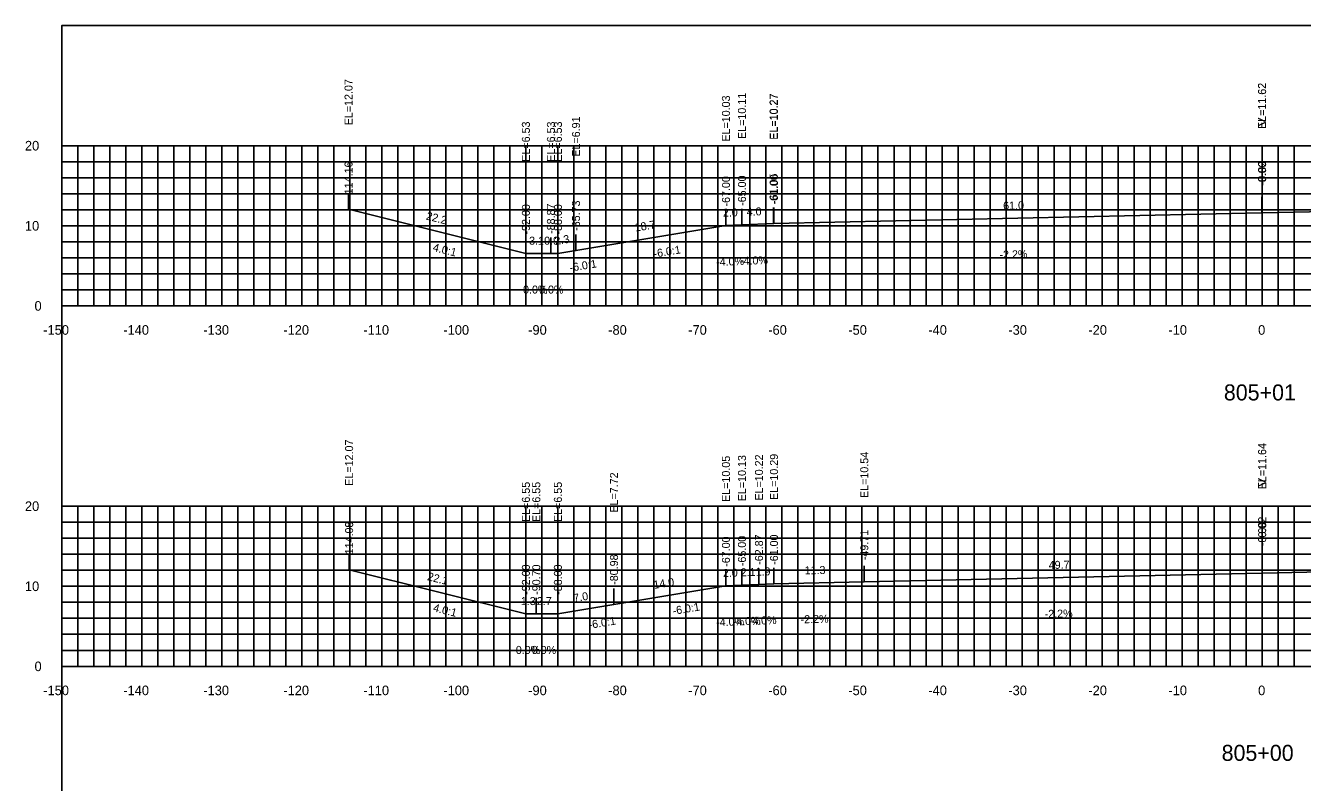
# Model space of a CAD drawing. Extents: x 1797419 to 1809236, y 248759 to 251512.
# Drawn here: x 1802824.4 to 1802984, y 249853.2 to 249947.7 of the extents above; entities that cross this region are included whole.
import ezdxf

# ---------------------------------------------------------------- set-up
doc = ezdxf.new("R2010")
doc.units = 0
for name, color, linetype in [('1', 7, 'Continuous'), ('10', 7, 'Continuous'), ('3', 7, 'Continuous'), ('31', 7, 'Continuous'), ('4', 7, 'Continuous'), ('60', 7, 'Continuous'), ('CL-CNST', 7, 'Continuous'), ('Level 62', 7, 'Continuous')]:
    doc.layers.add(name, color=color, linetype=linetype)

msp = doc.modelspace()

# ---------------------------------------------------------------- linework, layer by layer
for p, q in [((1802864.77, 249924.8), (1802864.77, 249926.8)), ((1802978.91, 249924.34), (1802978.91, 249926.34)), ((1802978.93, 249924.34), (1802978.93, 249926.34)), ((1802911.93, 249922.76), (1802911.93, 249924.76)), ((1802913.93, 249922.84), (1802913.93, 249924.84)), ((1802917.88, 249922.99), (1802917.88, 249924.99)), ((1802917.93, 249923), (1802917.93, 249925)), ((1802886.93, 249919.26), (1802886.93, 249921.26)), ((1802890.06, 249919.26), (1802890.06, 249921.26)), ((1802890.93, 249919.26), (1802890.93, 249921.26)), ((1802893.19, 249919.63), (1802893.19, 249921.63)), ((1802864.84, 249879.8), (1802864.84, 249881.8)), ((1802864.84, 249879.79), (1802864.84, 249881.79)), ((1802978.93, 249879.36), (1802978.93, 249881.36)), ((1802978.94, 249879.36), (1802978.94, 249881.36)), ((1802911.93, 249877.77), (1802911.93, 249879.77)), ((1802913.93, 249877.85), (1802913.93, 249879.85)), ((1802916.06, 249877.94), (1802916.06, 249879.94)), ((1802917.93, 249878.01), (1802917.93, 249880.01)), ((1802929.22, 249878.26), (1802929.22, 249880.26)), ((1802897.94, 249875.44), (1802897.94, 249877.44)), ((1802886.93, 249874.27), (1802886.93, 249876.27)), ((1802888.23, 249874.27), (1802888.23, 249876.27)), ((1802890.93, 249874.27), (1802890.93, 249876.27))]:
    msp.add_line(p, q)
msp.add_lwpolyline([(1802828.93, 249757.72), (1803128.93, 249757.72), (1803128.93, 249947.72), (1802828.93, 249947.72)], close=True)
at = {"layer": '60'}
for p, q in [((1802828.87, 249932.72), (1802828.93, 249932.72)), ((1802828.93, 249912.72), (1802828.93, 249932.72)), ((1802828.87, 249922.72), (1802828.93, 249922.72)), ((1802828.87, 249912.72), (1802828.93, 249912.72)), ((1802828.93, 249912.72), (1803128.93, 249912.72)), ((1802828.93, 249912.66), (1802828.93, 249912.72)), ((1802838.93, 249912.66), (1802838.93, 249912.72)), ((1802848.93, 249912.66), (1802848.93, 249912.72)), ((1802858.93, 249912.66), (1802858.93, 249912.72)), ((1802868.93, 249912.66), (1802868.93, 249912.72)), ((1802878.93, 249912.66), (1802878.93, 249912.72)), ((1802888.93, 249912.66), (1802888.93, 249912.72)), ((1802898.93, 249912.66), (1802898.93, 249912.72)), ((1802908.93, 249912.66), (1802908.93, 249912.72)), ((1802918.93, 249912.66), (1802918.93, 249912.72)), ((1802928.93, 249912.66), (1802928.93, 249912.72)), ((1802938.93, 249912.66), (1802938.93, 249912.72)), ((1802948.93, 249912.66), (1802948.93, 249912.72)), ((1802958.93, 249912.66), (1802958.93, 249912.72)), ((1802968.93, 249912.66), (1802968.93, 249912.72)), ((1802978.93, 249912.66), (1802978.93, 249912.72)), ((1802828.87, 249887.72), (1802828.93, 249887.72)), ((1802828.93, 249867.72), (1802828.93, 249887.72)), ((1802828.87, 249877.72), (1802828.93, 249877.72)), ((1802828.87, 249867.72), (1802828.93, 249867.72)), ((1802828.93, 249867.72), (1803128.93, 249867.72)), ((1802828.93, 249867.66), (1802828.93, 249867.72)), ((1802838.93, 249867.66), (1802838.93, 249867.72)), ((1802848.93, 249867.66), (1802848.93, 249867.72)), ((1802858.93, 249867.66), (1802858.93, 249867.72)), ((1802868.93, 249867.66), (1802868.93, 249867.72)), ((1802878.93, 249867.66), (1802878.93, 249867.72)), ((1802888.93, 249867.66), (1802888.93, 249867.72)), ((1802898.93, 249867.66), (1802898.93, 249867.72)), ((1802908.93, 249867.66), (1802908.93, 249867.72)), ((1802918.93, 249867.66), (1802918.93, 249867.72)), ((1802928.93, 249867.66), (1802928.93, 249867.72)), ((1802938.93, 249867.66), (1802938.93, 249867.72)), ((1802948.93, 249867.66), (1802948.93, 249867.72)), ((1802958.93, 249867.66), (1802958.93, 249867.72)), ((1802968.93, 249867.66), (1802968.93, 249867.72)), ((1802978.93, 249867.66), (1802978.93, 249867.72))]:
    msp.add_line(p, q, dxfattribs=at)
at = {"layer": 'CL-CNST'}
for points in [[(1802864.77, 249924.8), (1802886.93, 249919.26), (1802890.06, 249919.26), (1802890.93, 249919.26), (1802893.19, 249919.63), (1802911.93, 249922.76), (1802913.93, 249922.84), (1802917.88, 249922.99), (1802917.93, 249923), (1802978.91, 249924.34), (1802978.93, 249924.34), (1803004.61, 249924.9), (1803029.47, 249925.45), (1803033.47, 249925.29), (1803035.33, 249925.22), (1803035.47, 249925.21), (1803036.02, 249925.12), (1803056.47, 249921.71), (1803060.46, 249921.71), (1803093.13, 249923.34), (1803128.93, 249925.13)], [(1802864.84, 249879.8), (1802864.84, 249879.79), (1802886.93, 249874.27), (1802888.23, 249874.27), (1802890.93, 249874.27), (1802897.94, 249875.44), (1802911.93, 249877.77), (1802913.93, 249877.85), (1802916.06, 249877.94), (1802917.93, 249878.01), (1802929.22, 249878.26), (1802978.93, 249879.36), (1802978.94, 249879.36), (1803025.35, 249880.38), (1803029.55, 249880.47), (1803033.55, 249880.31), (1803035.55, 249880.23), (1803056.35, 249876.76), (1803056.55, 249876.73), (1803056.6, 249876.73), (1803060.55, 249876.73), (1803121.79, 249879.79), (1803128.93, 249880.15)]]:
    msp.add_lwpolyline(points, dxfattribs=at)
at = {"layer": 'Level 62'}
for p, q in [((1802828.93, 249932.72), (1803128.93, 249932.72)), ((1802828.93, 249912.72), (1802828.93, 249932.72)), ((1802830.93, 249912.72), (1802830.93, 249932.72)), ((1802832.93, 249912.72), (1802832.93, 249932.72)), ((1802834.93, 249912.72), (1802834.93, 249932.72)), ((1802836.93, 249912.72), (1802836.93, 249932.72)), ((1802838.93, 249912.72), (1802838.93, 249932.72)), ((1802840.93, 249912.72), (1802840.93, 249932.72)), ((1802842.93, 249912.72), (1802842.93, 249932.72)), ((1802844.93, 249912.72), (1802844.93, 249932.72)), ((1802846.93, 249912.72), (1802846.93, 249932.72)), ((1802848.93, 249912.72), (1802848.93, 249932.72)), ((1802850.93, 249912.72), (1802850.93, 249932.72)), ((1802852.93, 249912.72), (1802852.93, 249932.72)), ((1802854.93, 249912.72), (1802854.93, 249932.72)), ((1802856.93, 249912.72), (1802856.93, 249932.72)), ((1802858.93, 249912.72), (1802858.93, 249932.72)), ((1802860.93, 249912.72), (1802860.93, 249932.72)), ((1802862.93, 249912.72), (1802862.93, 249932.72)), ((1802864.93, 249912.72), (1802864.93, 249932.72)), ((1802866.93, 249912.72), (1802866.93, 249932.72)), ((1802868.93, 249912.72), (1802868.93, 249932.72)), ((1802870.93, 249912.72), (1802870.93, 249932.72)), ((1802872.93, 249912.72), (1802872.93, 249932.72)), ((1802874.93, 249912.72), (1802874.93, 249932.72)), ((1802876.93, 249912.72), (1802876.93, 249932.72)), ((1802878.93, 249912.72), (1802878.93, 249932.72)), ((1802880.93, 249912.72), (1802880.93, 249932.72)), ((1802882.93, 249912.72), (1802882.93, 249932.72)), ((1802884.93, 249912.72), (1802884.93, 249932.72)), ((1802886.93, 249912.72), (1802886.93, 249932.72)), ((1802888.93, 249912.72), (1802888.93, 249932.72)), ((1802890.93, 249912.72), (1802890.93, 249932.72)), ((1802892.93, 249912.72), (1802892.93, 249932.72)), ((1802894.93, 249912.72), (1802894.93, 249932.72)), ((1802896.93, 249912.72), (1802896.93, 249932.72)), ((1802898.93, 249912.72), (1802898.93, 249932.72)), ((1802900.93, 249912.72), (1802900.93, 249932.72)), ((1802902.93, 249912.72), (1802902.93, 249932.72)), ((1802904.93, 249912.72), (1802904.93, 249932.72)), ((1802906.93, 249912.72), (1802906.93, 249932.72)), ((1802908.93, 249912.72), (1802908.93, 249932.72)), ((1802910.93, 249912.72), (1802910.93, 249932.72)), ((1802912.93, 249912.72), (1802912.93, 249932.72)), ((1802914.93, 249912.72), (1802914.93, 249932.72)), ((1802916.93, 249912.72), (1802916.93, 249932.72)), ((1802918.93, 249912.72), (1802918.93, 249932.72)), ((1802920.93, 249912.72), (1802920.93, 249932.72)), ((1802922.93, 249912.72), (1802922.93, 249932.72)), ((1802924.93, 249912.72), (1802924.93, 249932.72)), ((1802926.93, 249912.72), (1802926.93, 249932.72)), ((1802928.93, 249912.72), (1802928.93, 249932.72)), ((1802930.93, 249912.72), (1802930.93, 249932.72)), ((1802932.93, 249912.72), (1802932.93, 249932.72)), ((1802934.93, 249912.72), (1802934.93, 249932.72)), ((1802936.93, 249912.72), (1802936.93, 249932.72)), ((1802938.93, 249912.72), (1802938.93, 249932.72)), ((1802940.93, 249912.72), (1802940.93, 249932.72)), ((1802942.93, 249912.72), (1802942.93, 249932.72)), ((1802944.93, 249912.72), (1802944.93, 249932.72)), ((1802946.93, 249912.72), (1802946.93, 249932.72)), ((1802948.93, 249912.72), (1802948.93, 249932.72)), ((1802950.93, 249912.72), (1802950.93, 249932.72)), ((1802952.93, 249912.72), (1802952.93, 249932.72)), ((1802954.93, 249912.72), (1802954.93, 249932.72)), ((1802956.93, 249912.72), (1802956.93, 249932.72)), ((1802958.93, 249912.72), (1802958.93, 249932.72)), ((1802960.93, 249912.72), (1802960.93, 249932.72)), ((1802962.93, 249912.72), (1802962.93, 249932.72)), ((1802964.93, 249912.72), (1802964.93, 249932.72)), ((1802966.93, 249912.72), (1802966.93, 249932.72)), ((1802968.93, 249912.72), (1802968.93, 249932.72)), ((1802970.93, 249912.72), (1802970.93, 249932.72)), ((1802972.93, 249912.72), (1802972.93, 249932.72)), ((1802974.93, 249912.72), (1802974.93, 249932.72)), ((1802976.93, 249912.72), (1802976.93, 249932.72)), ((1802978.93, 249912.72), (1802978.93, 249932.72)), ((1802980.93, 249912.72), (1802980.93, 249932.72)), ((1802982.93, 249912.72), (1802982.93, 249932.72)), ((1802828.93, 249930.72), (1803128.93, 249930.72)), ((1802828.93, 249928.72), (1803128.93, 249928.72)), ((1802828.93, 249926.72), (1803128.93, 249926.72)), ((1802828.93, 249924.72), (1803128.93, 249924.72)), ((1802828.93, 249922.72), (1803128.93, 249922.72)), ((1802828.93, 249920.72), (1803128.93, 249920.72)), ((1802828.93, 249918.72), (1803128.93, 249918.72)), ((1802828.93, 249916.72), (1803128.93, 249916.72)), ((1802828.93, 249914.72), (1803128.93, 249914.72)), ((1802828.93, 249912.72), (1803128.93, 249912.72)), ((1802828.93, 249887.72), (1803128.93, 249887.72)), ((1802828.93, 249867.72), (1802828.93, 249887.72)), ((1802830.93, 249867.72), (1802830.93, 249887.72)), ((1802832.93, 249867.72), (1802832.93, 249887.72)), ((1802834.93, 249867.72), (1802834.93, 249887.72)), ((1802836.93, 249867.72), (1802836.93, 249887.72)), ((1802838.93, 249867.72), (1802838.93, 249887.72)), ((1802840.93, 249867.72), (1802840.93, 249887.72)), ((1802842.93, 249867.72), (1802842.93, 249887.72)), ((1802844.93, 249867.72), (1802844.93, 249887.72)), ((1802846.93, 249867.72), (1802846.93, 249887.72)), ((1802848.93, 249867.72), (1802848.93, 249887.72)), ((1802850.93, 249867.72), (1802850.93, 249887.72)), ((1802852.93, 249867.72), (1802852.93, 249887.72)), ((1802854.93, 249867.72), (1802854.93, 249887.72)), ((1802856.93, 249867.72), (1802856.93, 249887.72)), ((1802858.93, 249867.72), (1802858.93, 249887.72)), ((1802860.93, 249867.72), (1802860.93, 249887.72)), ((1802862.93, 249867.72), (1802862.93, 249887.72)), ((1802864.93, 249867.72), (1802864.93, 249887.72)), ((1802866.93, 249867.72), (1802866.93, 249887.72)), ((1802868.93, 249867.72), (1802868.93, 249887.72)), ((1802870.93, 249867.72), (1802870.93, 249887.72)), ((1802872.93, 249867.72), (1802872.93, 249887.72)), ((1802874.93, 249867.72), (1802874.93, 249887.72)), ((1802876.93, 249867.72), (1802876.93, 249887.72)), ((1802878.93, 249867.72), (1802878.93, 249887.72)), ((1802880.93, 249867.72), (1802880.93, 249887.72)), ((1802882.93, 249867.72), (1802882.93, 249887.72)), ((1802884.93, 249867.72), (1802884.93, 249887.72)), ((1802886.93, 249867.72), (1802886.93, 249887.72)), ((1802888.93, 249867.72), (1802888.93, 249887.72)), ((1802890.93, 249867.72), (1802890.93, 249887.72)), ((1802892.93, 249867.72), (1802892.93, 249887.72)), ((1802894.93, 249867.72), (1802894.93, 249887.72)), ((1802896.93, 249867.72), (1802896.93, 249887.72)), ((1802898.93, 249867.72), (1802898.93, 249887.72)), ((1802900.93, 249867.72), (1802900.93, 249887.72)), ((1802902.93, 249867.72), (1802902.93, 249887.72)), ((1802904.93, 249867.72), (1802904.93, 249887.72)), ((1802906.93, 249867.72), (1802906.93, 249887.72)), ((1802908.93, 249867.72), (1802908.93, 249887.72)), ((1802910.93, 249867.72), (1802910.93, 249887.72)), ((1802912.93, 249867.72), (1802912.93, 249887.72)), ((1802914.93, 249867.72), (1802914.93, 249887.72)), ((1802916.93, 249867.72), (1802916.93, 249887.72)), ((1802918.93, 249867.72), (1802918.93, 249887.72)), ((1802920.93, 249867.72), (1802920.93, 249887.72)), ((1802922.93, 249867.72), (1802922.93, 249887.72)), ((1802924.93, 249867.72), (1802924.93, 249887.72)), ((1802926.93, 249867.72), (1802926.93, 249887.72)), ((1802928.93, 249867.72), (1802928.93, 249887.72)), ((1802930.93, 249867.72), (1802930.93, 249887.72)), ((1802932.93, 249867.72), (1802932.93, 249887.72)), ((1802934.93, 249867.72), (1802934.93, 249887.72)), ((1802936.93, 249867.72), (1802936.93, 249887.72)), ((1802938.93, 249867.72), (1802938.93, 249887.72)), ((1802940.93, 249867.72), (1802940.93, 249887.72)), ((1802942.93, 249867.72), (1802942.93, 249887.72)), ((1802944.93, 249867.72), (1802944.93, 249887.72)), ((1802946.93, 249867.72), (1802946.93, 249887.72)), ((1802948.93, 249867.72), (1802948.93, 249887.72)), ((1802950.93, 249867.72), (1802950.93, 249887.72)), ((1802952.93, 249867.72), (1802952.93, 249887.72)), ((1802954.93, 249867.72), (1802954.93, 249887.72)), ((1802956.93, 249867.72), (1802956.93, 249887.72)), ((1802958.93, 249867.72), (1802958.93, 249887.72)), ((1802960.93, 249867.72), (1802960.93, 249887.72)), ((1802962.93, 249867.72), (1802962.93, 249887.72)), ((1802964.93, 249867.72), (1802964.93, 249887.72)), ((1802966.93, 249867.72), (1802966.93, 249887.72)), ((1802968.93, 249867.72), (1802968.93, 249887.72)), ((1802970.93, 249867.72), (1802970.93, 249887.72)), ((1802972.93, 249867.72), (1802972.93, 249887.72)), ((1802974.93, 249867.72), (1802974.93, 249887.72)), ((1802976.93, 249867.72), (1802976.93, 249887.72)), ((1802978.93, 249867.72), (1802978.93, 249887.72)), ((1802980.93, 249867.72), (1802980.93, 249887.72)), ((1802982.93, 249867.72), (1802982.93, 249887.72)), ((1802828.93, 249885.72), (1803128.93, 249885.72)), ((1802828.93, 249883.72), (1803128.93, 249883.72)), ((1802828.93, 249881.72), (1803128.93, 249881.72)), ((1802828.93, 249879.72), (1803128.93, 249879.72)), ((1802828.93, 249877.72), (1803128.93, 249877.72)), ((1802828.93, 249875.72), (1803128.93, 249875.72)), ((1802828.93, 249873.72), (1803128.93, 249873.72)), ((1802828.93, 249871.72), (1803128.93, 249871.72)), ((1802828.93, 249869.72), (1803128.93, 249869.72)), ((1802828.93, 249867.72), (1803128.93, 249867.72))]:
    msp.add_line(p, q, dxfattribs=at)

# ---------------------------------------------------------------- texts
for s, rotation, p in [('4.0:1', 345.9642, (1802875.24, 249919.6)), ('-6.0:1', 9.4623, (1802902.97, 249918.73)), ('-6.0:1', 9.4623, (1802892.47, 249916.98)), ('-6.0:1', 9.4623, (1802905.35, 249874.14)), ('4.0:1', 345.9644, (1802875.28, 249874.61)), ('-6.0:1', 9.4623, (1802894.85, 249872.39))]:
    msp.add_text(s, height=1, rotation=rotation).set_placement(p)
at = {"layer": '1'}
for s, p in [('805+01', (1802974.15, 249900.92)), ('805+00', (1802973.87, 249855.92))]:
    msp.add_text(s, height=2, dxfattribs=at).set_placement(p)
at = {"layer": '10'}
for s, p in [('-150', (1802826.62, 249909.12)), ('-140', (1802836.62, 249909.12)), ('-130', (1802846.62, 249909.12)), ('-120', (1802856.62, 249909.12)), ('-110', (1802866.62, 249909.12)), ('-100', (1802876.62, 249909.12)), ('-90', (1802887.22, 249909.12)), ('-80', (1802897.22, 249909.12)), ('-70', (1802907.22, 249909.12)), ('-60', (1802917.22, 249909.12)), ('-50', (1802927.22, 249909.12)), ('-40', (1802937.22, 249909.12)), ('-30', (1802947.22, 249909.12)), ('-20', (1802957.22, 249909.12)), ('-10', (1802967.22, 249909.12)), ('0', (1802978.43, 249909.12)), ('-150', (1802826.62, 249864.12)), ('-140', (1802836.62, 249864.12)), ('-130', (1802846.62, 249864.12)), ('-120', (1802856.62, 249864.12)), ('-110', (1802866.62, 249864.12)), ('-100', (1802876.62, 249864.12)), ('-90', (1802887.22, 249864.12)), ('-80', (1802897.22, 249864.12)), ('-70', (1802907.22, 249864.12)), ('-60', (1802917.22, 249864.12)), ('-50', (1802927.22, 249864.12)), ('-40', (1802937.22, 249864.12)), ('-30', (1802947.22, 249864.12)), ('-20', (1802957.22, 249864.12)), ('-10', (1802967.22, 249864.12)), ('0', (1802978.43, 249864.12))]:
    msp.add_text(s, height=1.2, dxfattribs=at).set_placement(p)
at = {"layer": '3'}
for s, p in [('EL=12.07', (1802865.27, 249935.27)), ('EL=11.62', (1802979.41, 249934.81)), ('EL=11.62', (1802979.43, 249934.81)), ('EL=10.03', (1802912.43, 249933.23)), ('EL=10.11', (1802914.43, 249933.56)), ('EL=10.27', (1802918.38, 249933.47)), ('EL=10.27', (1802918.43, 249933.47)), ('EL=6.91', (1802893.69, 249931.35)), ('EL=6.53', (1802887.43, 249930.72)), ('EL=6.53', (1802890.56, 249930.72)), ('EL=6.53', (1802891.43, 249930.72)), ('-114.16', (1802865.27, 249926.21)), ('-0.02', (1802979.41, 249927.79)), ('-0.00', (1802979.43, 249927.71)), ('-67.00', (1802912.43, 249925.13)), ('-65.00', (1802914.43, 249925.21)), ('-61.05', (1802918.38, 249925.45)), ('-61.00', (1802918.43, 249925.37)), ('-92.00', (1802887.43, 249921.63)), ('-88.87', (1802890.56, 249921.71)), ('-88.00', (1802891.43, 249921.63)), ('-85.73', (1802893.69, 249922.09)), ('EL=12.07', (1802865.34, 249890.27)), ('EL=12.07', (1802865.34, 249890.27)), ('EL=11.64', (1802979.43, 249889.83)), ('EL=11.64', (1802979.44, 249889.83)), ('EL=10.05', (1802912.43, 249888.25)), ('EL=10.13', (1802914.43, 249888.33)), ('EL=10.22', (1802916.56, 249888.41)), ('EL=10.29', (1802918.43, 249888.49)), ('EL=10.54', (1802929.72, 249888.74)), ('EL=7.72', (1802898.44, 249886.91)), ('EL=6.55', (1802887.43, 249885.74)), ('EL=6.55', (1802888.73, 249885.74)), ('EL=6.55', (1802891.43, 249885.74)), ('-114.09', (1802865.34, 249881.26)), ('-114.08', (1802865.34, 249881.26)), ('-0.00', (1802979.43, 249882.73)), ('0.02', (1802979.44, 249883.8)), ('-67.00', (1802912.43, 249880.15)), ('-65.00', (1802914.43, 249880.23)), ('-62.87', (1802916.56, 249880.4)), ('-61.00', (1802918.43, 249880.39)), ('-49.71', (1802929.72, 249880.97)), ('-80.98', (1802898.44, 249877.9)), ('-92.00', (1802887.43, 249876.65)), ('-90.70', (1802888.73, 249876.65)), ('-88.00', (1802891.43, 249876.65))]:
    msp.add_text(s, height=1, rotation=90, dxfattribs=at).set_placement(p)
at = {"layer": '31'}
for s, p in [('20', (1802824.33, 249932.12)), ('10', (1802824.33, 249922.12)), ('0', (1802825.53, 249912.12)), ('20', (1802824.33, 249887.12)), ('10', (1802824.33, 249877.12)), ('0', (1802825.53, 249867.12))]:
    msp.add_text(s, height=1.2, dxfattribs=at).set_placement(p)
at = {"layer": '4'}
for s, rotation, p in [('61.0', 1.2603, (1802946.58, 249924.73)), ('22.2', 345.9642, (1802874.39, 249923.52)), ('2.0', 2.2903, (1802911.56, 249923.84)), ('4.0', 2.2909, (1802914.54, 249923.96)), ('18.7', 9.4623, (1802900.62, 249921.99)), ('2.3', 9.4623, (1802890.61, 249920.32)), ('-4.0%', 2.2903, (1802910.72, 249917.7)), ('-4.0%', 2.2909, (1802913.7, 249917.82)), ('-2.2%', 1.2603, (1802946.12, 249918.62)), ('49.7', 1.2603, (1802952.27, 249879.87)), ('22.1', 345.9644, (1802874.55, 249878.5)), ('2.0', 2.2903, (1802911.56, 249878.86)), ('2.1', 2.2909, (1802913.79, 249878.95)), ('1.9', 2.2909, (1802915.66, 249879.02)), ('11.3', 1.2603, (1802921.77, 249879.2)), ('14.0', 9.4623, (1802902.96, 249877.39)), ('7.0', 9.4623, (1802892.95, 249875.73)), ('-2.2%', 1.2603, (1802921.27, 249873.09)), ('-2.2%', 1.2603, (1802951.77, 249873.76)), ('-4.0%', 2.2903, (1802910.72, 249872.72)), ('-4.0%', 2.2909, (1802912.78, 249872.8)), ('-4.0%', 2.2909, (1802914.78, 249872.88))]:
    msp.add_text(s, height=1, rotation=rotation, dxfattribs=at).set_placement(p)
for s, p in [('3.1', (1802887.33, 249920.36)), ('0.9', (1802889.21, 249920.36)), ('0.0%', (1802886.58, 249914.26)), ('0.0%', (1802888.58, 249914.26)), ('1.3', (1802886.3, 249875.37)), ('2.7', (1802888.3, 249875.37)), ('0.0%', (1802885.67, 249869.27)), ('0.0%', (1802887.67, 249869.27))]:
    msp.add_text(s, height=1, dxfattribs=at).set_placement(p)
at = {"layer": '60'}
for s, height, p in [('>', 1.5, (1802978.32, 249934.97)), ('-', 0.0001, (1802828.93, 249912.72)), ('>', 1.5, (1802978.32, 249889.97)), ('-', 0.0001, (1802828.93, 249867.72))]:
    msp.add_text(s, height=height, dxfattribs=at).set_placement(p)

doc.saveas('drawing.dxf')
